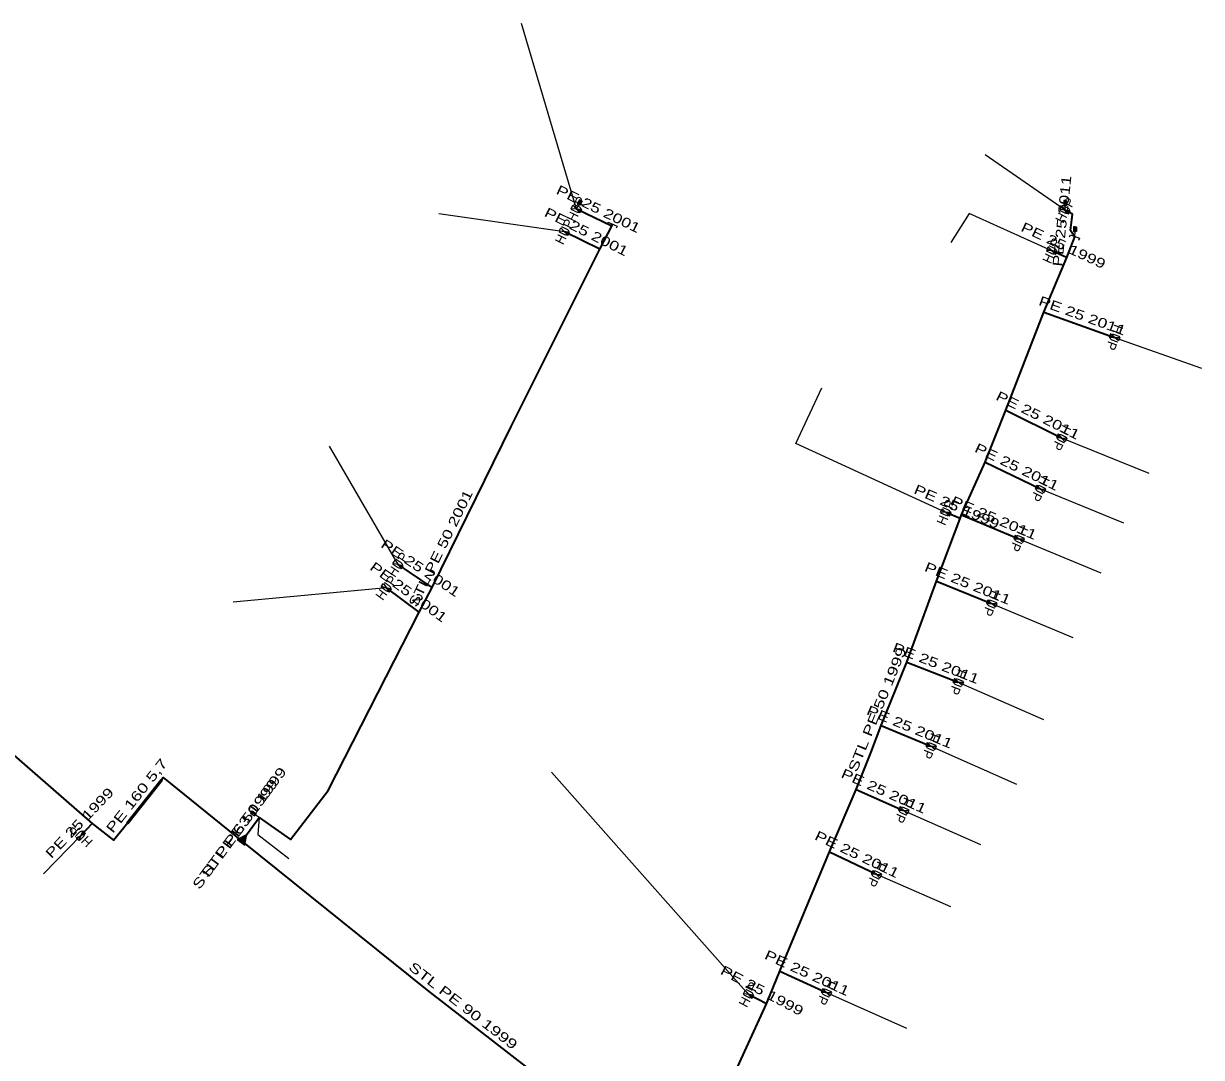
# Model space of a CAD drawing. Extents: x -737484 to -734496, y -1033882 to -1030666.
# Drawn here: x -735749 to -735627.2, y -1032516.8 to -1032410 of the extents above; entities that cross this region are included whole.
import ezdxf
from ezdxf.enums import TextEntityAlignment as Align

# ---------------------------------------------------------------- set-up
doc = ezdxf.new("R2010")
doc.units = 0
doc.header["$LTSCALE"] = 0.4
for name, color, linetype, lineweight in [('1', 7, 'Continuous', 13), ('18', 7, 'Continuous', 60), ('22', 7, 'Continuous', 25), ('5', 7, 'Continuous', 35), ('7', 7, 'Continuous', 35)]:
    doc.layers.add(name, color=color, linetype=linetype, lineweight=lineweight)
doc.layers.add('2', color=7, linetype='Continuous')

msp = doc.modelspace()

# ---------------------------------------------------------------- linework, layer by layer
at = {"layer": '1'}
for p, q in [((-735691.835, -1032429.184), (-735691.615, -1032428.734)), ((-735691.515, -1032428.7), (-735691.362, -1032428.385)), ((-735641.328, -1032429.3), (-735641.328, -1032428.8)), ((-735641.253, -1032428.725), (-735641.253, -1032428.375)), ((-735640.314, -1032432.01), (-735640.305, -1032431.51)), ((-735640.228, -1032431.436), (-735640.222, -1032431.086)), ((-735725.051, -1032491.669), (-735725.334, -1032491.463)), ((-735724.63, -1032492.068), (-735725.034, -1032491.774))]:
    msp.add_line(p, q, dxfattribs=at)
for points in [[(-735691.396, -1032428.285), (-735691.531, -1032428.219), (-735691.75, -1032428.668), (-735691.615, -1032428.734)], [(-735692.371, -1032429.144), (-735692.195, -1032428.785), (-735691.472, -1032429.582), (-735691.296, -1032429.223)], [(-735691.396, -1032428.285), (-735691.261, -1032428.35), (-735691.48, -1032428.8), (-735691.615, -1032428.734)], [(-735691.38, -1032428.335), (-735691.312, -1032428.368), (-735691.498, -1032428.75), (-735691.566, -1032428.717)], [(-735641.863, -1032429.241), (-735641.675, -1032428.888), (-735640.98, -1032429.711), (-735640.792, -1032429.358)], [(-735641.328, -1032428.3), (-735641.478, -1032428.3), (-735641.478, -1032428.8), (-735641.328, -1032428.8)], [(-735641.328, -1032428.3), (-735641.178, -1032428.3), (-735641.178, -1032428.8), (-735641.328, -1032428.8)], [(-735641.291, -1032428.338), (-735641.216, -1032428.338), (-735641.216, -1032428.763), (-735641.291, -1032428.763)], [(-735693.616, -1032431.476), (-735693.44, -1032431.117), (-735692.717, -1032431.914), (-735692.541, -1032431.555)], [(-735640.296, -1032431.01), (-735640.446, -1032431.007), (-735640.455, -1032431.507), (-735640.305, -1032431.51)], [(-735640.296, -1032431.01), (-735640.146, -1032431.012), (-735640.155, -1032431.512), (-735640.305, -1032431.51)], [(-735640.26, -1032431.048), (-735640.185, -1032431.05), (-735640.192, -1032431.475), (-735640.267, -1032431.473)], [(-735643.234, -1032433.456), (-735643.065, -1032433.094), (-735642.328, -1032433.879), (-735642.159, -1032433.517)], [(-735635.689, -1032442.43), (-735635.826, -1032442.805), (-735636.629, -1032442.088), (-735636.766, -1032442.463)], [(-735641.154, -1032452.861), (-735641.33, -1032453.22), (-735642.053, -1032452.423), (-735642.229, -1032452.782)], [(-735643.353, -1032458.137), (-735643.529, -1032458.496), (-735644.252, -1032457.699), (-735644.428, -1032458.058)], [(-735654.197, -1032460.516), (-735654.041, -1032460.148), (-735653.276, -1032460.907), (-735653.12, -1032460.539)], [(-735645.558, -1032463.271), (-735645.714, -1032463.639), (-735646.479, -1032462.88), (-735646.635, -1032463.248)], [(-735710.8, -1032465.805), (-735710.576, -1032465.473), (-735709.971, -1032466.364), (-735709.747, -1032466.032)], [(-735712.005, -1032468.184), (-735711.769, -1032467.861), (-735711.196, -1032468.772), (-735710.96, -1032468.449)], [(-735648.384, -1032469.934), (-735648.534, -1032470.305), (-735649.311, -1032469.56), (-735649.461, -1032469.931)], [(-735651.841, -1032478.055), (-735651.984, -1032478.428), (-735652.775, -1032477.697), (-735652.918, -1032478.07)], [(-735654.66, -1032484.678), (-735654.81, -1032485.049), (-735655.587, -1032484.304), (-735655.737, -1032484.675)], [(-735725.439, -1032491.48), (-735725.527, -1032491.601), (-735725.122, -1032491.895), (-735725.034, -1032491.774)], [(-735725.439, -1032491.48), (-735725.35, -1032491.358), (-735724.946, -1032491.652), (-735725.034, -1032491.774)], [(-735725.386, -1032491.472), (-735725.342, -1032491.411), (-735724.998, -1032491.661), (-735725.042, -1032491.722)], [(-735657.479, -1032491.338), (-735657.642, -1032491.704), (-735658.393, -1032490.931), (-735658.556, -1032491.297)], [(-735743.271, -1032494.416), (-735743.559, -1032494.138), (-735742.576, -1032493.697), (-735742.864, -1032493.419)], [(-735726.919, -1032494.317), (-735726.12, -1032494.919), (-735725.918, -1032493.819)], [(-735726.189, -1032494.741), (-735726.052, -1032493.998), (-735726.729, -1032494.335)], [(-735726.187, -1032494.176), (-735726.54, -1032494.352), (-735726.258, -1032494.565)], [(-735660.301, -1032497.96), (-735660.477, -1032498.319), (-735661.2, -1032497.522), (-735661.376, -1032497.881)], [(-735665.471, -1032510.152), (-735665.64, -1032510.514), (-735666.377, -1032509.729), (-735666.546, -1032510.091)], [(-735674.583, -1032510.28), (-735674.395, -1032509.927), (-735673.7, -1032510.75), (-735673.512, -1032510.397)]]:
    msp.add_lwpolyline(points, close=True, dxfattribs=at)
for points in [[(-735688.661, -1032430.773), (-735688.564, -1032430.543), (-735687.643, -1032430.934), (-735687.741, -1032431.164)], [(-735640.87, -1032432.064), (-735640.78, -1032431.83), (-735639.847, -1032432.189), (-735639.936, -1032432.422)], [(-735724.629, -1032492.068), (-735724.76, -1032493.804), (-735721.56, -1032496.293)]]:
    msp.add_lwpolyline(points, dxfattribs=at)
at = {"layer": '18'}
msp.add_line((-735734.74, -1032488.18), (-735738.263, -1032492.658), dxfattribs=at)
at = {"layer": '22'}
for p, q in [((-735691.834, -1032429.184), (-735697.527, -1032410.011)), ((-735641.328, -1032429.3), (-735649.596, -1032423.587)), ((-735693.079, -1032431.516), (-735706.061, -1032429.678)), ((-735636.228, -1032442.447), (-735627.239, -1032445.614)), ((-735710.274, -1032465.919), (-735717.379, -1032453.685)), ((-735641.692, -1032452.822), (-735632.663, -1032456.462)), ((-735643.891, -1032458.098), (-735635.309, -1032461.621)), ((-735646.097, -1032463.26), (-735637.624, -1032466.781)), ((-735711.483, -1032468.317), (-735727.324, -1032469.803)), ((-735648.923, -1032469.933), (-735640.534, -1032473.461)), ((-735652.38, -1032478.063), (-735643.577, -1032481.928)), ((-735655.199, -1032484.677), (-735646.355, -1032488.609)), ((-735674.048, -1032510.339), (-735694.423, -1032487.367)), ((-735658.018, -1032491.318), (-735650.059, -1032494.827)), ((-735743.068, -1032493.918), (-735746.917, -1032497.874)), ((-735660.839, -1032497.921), (-735653.168, -1032501.243)), ((-735666.009, -1032510.122), (-735657.732, -1032513.811))]:
    msp.add_line(p, q, dxfattribs=at)
for points in [[(-735642.699, -1032433.489), (-735651.263, -1032429.633), (-735653.144, -1032432.644)], [(-735653.659, -1032460.53), (-735669.157, -1032453.391), (-735666.46, -1032447.66)]]:
    msp.add_lwpolyline(points, dxfattribs=at)
at = {"layer": '5'}
for p, q in [((-735726.219, -1032494.219), (-735724.629, -1032492.068)), ((-735726.42, -1032494.49), (-735726.219, -1032494.219))]:
    msp.add_line(p, q, dxfattribs=at)
for points in [[(-735724.629, -1032492.068), (-735721.407, -1032494.318), (-735717.515, -1032489.264), (-735708.083, -1032470.821), (-735706.75, -1032468.284), (-735698.584, -1032451.633), (-735689.438, -1032433.331), (-735688.195, -1032430.958), (-735688.104, -1032430.739)], [(-735816.541, -1032432.858), (-735812.07, -1032436.32), (-735808.74, -1032436.48), (-735779.39, -1032460.59), (-735768.31, -1032470.07), (-735756.86, -1032479.88), (-735753.52, -1032482.57), (-735741.88, -1032492.68), (-735739.7, -1032494.41), (-735738.17, -1032492.54), (-735734.74, -1032488.18), (-735734.54, -1032487.93), (-735726.42, -1032494.49)], [(-735681.44, -1032529.48), (-735677.84, -1032524.44), (-735676.689, -1032521.092), (-735672.19, -1032511.32), (-735670.813, -1032507.929), (-735665.694, -1032495.605), (-735662.919, -1032489.153), (-735661.42, -1032485.36), (-735660.348, -1032482.554), (-735657.69, -1032476.014), (-735654.612, -1032467.632), (-735652.186, -1032461.166), (-735652.035, -1032460.762), (-735649.606, -1032455.339), (-735647.469, -1032449.948), (-735643.535, -1032439.827), (-735641.15, -1032434.19), (-735640.323, -1032432.034), (-735640.314, -1032432.01)], [(-735726.42, -1032494.49), (-735707.27, -1032509.88), (-735681.64, -1032529.76), (-735681.44, -1032529.48)]]:
    msp.add_lwpolyline(points, dxfattribs=at)
at = {"layer": '7'}
for p, q in [((-735688.195, -1032430.958), (-735691.834, -1032429.184)), ((-735689.438, -1032433.331), (-735693.079, -1032431.516)), ((-735643.535, -1032439.827), (-735636.228, -1032442.447)), ((-735647.469, -1032449.948), (-735641.692, -1032452.822)), ((-735649.606, -1032455.339), (-735643.891, -1032458.098)), ((-735652.186, -1032461.166), (-735653.659, -1032460.528)), ((-735652.035, -1032460.762), (-735646.097, -1032463.26)), ((-735706.75, -1032468.284), (-735710.274, -1032465.919)), ((-735708.083, -1032470.821), (-735711.483, -1032468.317)), ((-735654.612, -1032467.632), (-735648.923, -1032469.933)), ((-735657.69, -1032476.014), (-735652.38, -1032478.063)), ((-735660.348, -1032482.554), (-735655.199, -1032484.677)), ((-735662.919, -1032489.153), (-735658.018, -1032491.318)), ((-735741.88, -1032492.68), (-735743.068, -1032493.918)), ((-735665.694, -1032495.605), (-735660.839, -1032497.921)), ((-735670.813, -1032507.929), (-735666.009, -1032510.122)), ((-735672.19, -1032511.32), (-735674.048, -1032510.339))]:
    msp.add_line(p, q, dxfattribs=at)
for points in [[(-735640.323, -1032432.034), (-735640.758, -1032431.407), (-735640.581, -1032429.697), (-735641.328, -1032429.3)], [(-735641.15, -1032434.19), (-735641.184, -1032434.193), (-735642.697, -1032433.487)]]:
    msp.add_lwpolyline(points, dxfattribs=at)

# ---------------------------------------------------------------- texts
at = {"layer": '18', "width": 1.4}
msp.add_text('PE 160 5,7', height=1, rotation=51.807, dxfattribs=at).set_placement((-735736.8936, -1032490.1092), align=Align.CENTER)
at = {"layer": '2', "width": 0.95}
for rotation, p in [(64, (-735691.3845, -1032429.4027)), (62, (-735640.886, -1032429.5342)), (64, (-735692.6295, -1032431.7347)), (65, (-735642.2434, -1032433.6978)), (250, (-735636.6977, -1032442.2755)), (244, (-735642.1405, -1032452.6023)), (244, (-735644.3395, -1032457.8783)), (67, (-735653.1987, -1032460.7229)), (247, (-735646.5563, -1032463.0641)), (56, (-735709.8591, -1032466.1981)), (54, (-735711.078, -1032468.6104)), (248, (-735649.386, -1032469.7452)), (249, (-735652.8463, -1032477.8833)), (248, (-735655.662, -1032484.4892)), (246, (-735658.4747, -1032491.1141)), (136, (-735742.7202, -1032493.5576)), (244, (-735661.2875, -1032497.7013)), (62, (-735673.606, -1032510.5732)), (245, (-735666.4616, -1032509.9102))]:
    msp.add_text('HUP', height=1, rotation=rotation, dxfattribs=at).set_placement(p, align=Align.CENTER)
at = {"layer": '5'}
for s, rotation, width, p in [('STL PE 50 2001', 63.876, 1.35, (-735705.4297, -1032464.4572)), ('STL PE 50 1999', 67.882, 1.4, (-735660.2869, -1032481.0778)), ('STL PE 50 1999', 53.529, 1.4, (-735725.8262, -1032492.8457)), ('STL PE 63 1999', 53.436, 1.4, (-735726.7201, -1032494.0559)), ('STL PE 90 1999', 322.201, 1.4, (-735703.8544, -1032511.8952))]:
    msp.add_text(s, height=1, rotation=rotation, dxfattribs=dict(at, width=width)).set_placement(p, align=Align.CENTER)
at = {"layer": '7', "width": 1.35}
for s, rotation, p in [('PE 25 2001', 334.011, (-735689.7946, -1032429.6207)), ('PE 25 2011', 84.09, (-735641.1624, -1032430.459)), ('PE 25 2001', 333.504, (-735691.0351, -1032431.9751)), ('PE 25 1999', 334.985, (-735641.7129, -1032433.3934)), ('PE 25 2011', 340.274, (-735639.7123, -1032440.6659)), ('PE 25 2011', 333.55, (-735644.3572, -1032450.9368)), ('PE 25 2011', 334.23, (-735646.5309, -1032456.2674)), ('PE 25 1999', 336.581, (-735652.7232, -1032460.3874)), ('PE 25 2011', 337.184, (-735648.8719, -1032461.5497)), ('PE 25 2001', 326.134, (-735708.2331, -1032466.686)), ('PE 25 2001', 323.629, (-735709.486, -1032469.1661)), ('PE 25 2011', 337.978, (-735651.5795, -1032468.3185)), ('PE 25 2011', 338.9, (-735654.8545, -1032476.572)), ('PE 25 2011', 337.593, (-735657.5826, -1032483.1529)), ('PE 25 2011', 336.167, (-735660.266, -1032489.7777)), ('PE 25 1999', 46.181, (-735742.834, -1032492.9522)), ('PE 25 2011', 334.497, (-735663.0503, -1032496.3116)), ('PE 25 2011', 335.464, (-735668.2026, -1032508.5705)), ('PE 25 1999', 332.167, (-735672.885, -1032510.3868))]:
    msp.add_text(s, height=1, rotation=rotation, dxfattribs=at).set_placement(p, align=Align.CENTER)

doc.saveas('drawing.dxf')
